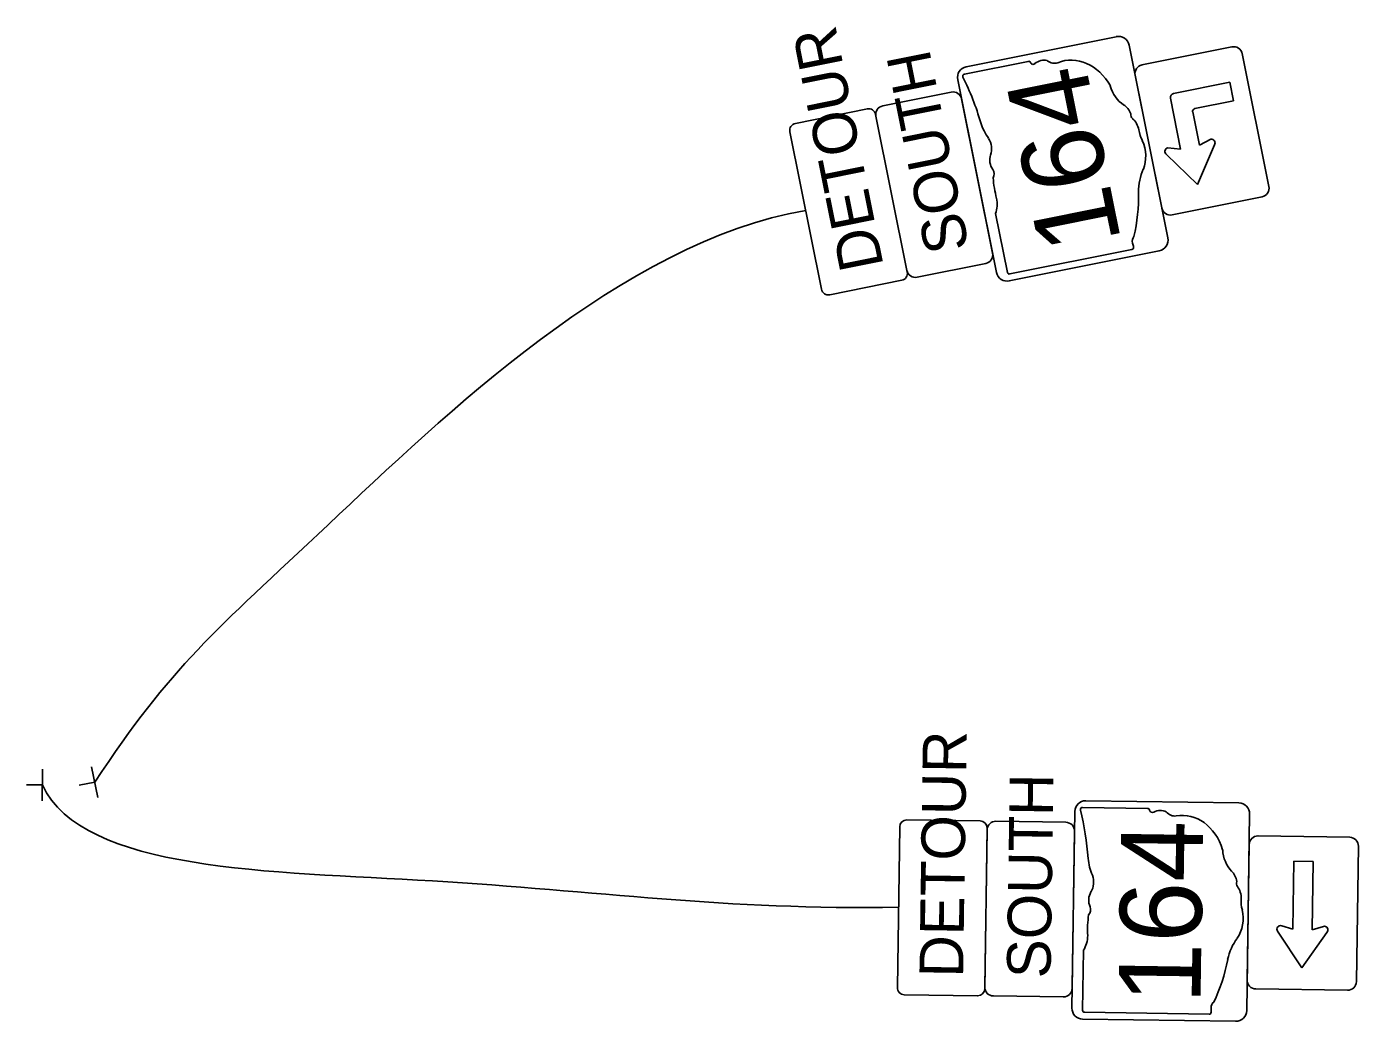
# Model space of a CAD drawing. Extents: x 0 to 1214, y 0 to 883.
# Drawn here: x 203.8 to 356.2, y 531.6 to 645.4 of the extents above; entities that cross this region are included whole.
import ezdxf

# ---------------------------------------------------------------- set-up
doc = ezdxf.new("R2010")
doc.units = 0
for name, color, linetype in [('GM_X_Minor_Lake', 7, 'Continuous'), ('GM_X_Minor_River', 7, 'Continuous'), ('SH_Data', 7, 'Continuous')]:
    doc.layers.add(name, color=color, linetype=linetype)

msp = doc.modelspace()

# ---------------------------------------------------------------- linework, layer by layer
at = {"layer": 'GM_X_Minor_Lake'}
for p, q in [((343.72, 551.84), (343.49, 536.34)), ((355.23, 552.67), (344.73, 552.82)), ((355.99, 536.15), (356.22, 551.65)), ((348.73, 542.14), (348.85, 549.95)), ((348.85, 549.95), (351.03, 549.91)), ((351.03, 549.91), (350.92, 542.1)), ((347.45, 542.55), (348.73, 542.14)), ((350.92, 542.1), (352.21, 542.48)), ((349.76, 537.74), (346.98, 541.92)), ((352.62, 541.78), (349.76, 537.74)), ((344.47, 535.32), (354.97, 535.17))]:
    msp.add_line(p, q, dxfattribs=at)
for centre, radius, start, end in [((344.72, 551.82), 1, 89.1557, 179.1557), ((355.22, 551.67), 1, 359.1557, 89.1557), ((347.32, 542.16), 0.417, 71.9511, 213.7445), ((352.32, 542.08), 0.417, 314.1461, 106.3603), ((344.49, 536.32), 1, 179.1557, 269.1557), ((354.99, 536.17), 1, 269.1557, 359.1557)]:
    msp.add_arc(centre, radius, start, end, dxfattribs=at)
at = {"layer": 'GM_X_Minor_River'}
for p, q in [((331.46, 641.06), (341.75, 643.13)), ((318.44, 641.47), (311.14, 640)), ((318.44, 641.47), (318.44, 641.47)), ((342.93, 642.35), (345.98, 627.15)), ((333.73, 624.69), (330.68, 639.88)), ((341.51, 639.1), (335.08, 637.8)), ((341.94, 636.95), (341.51, 639.1)), ((301.8, 636.38), (309.64, 637.95)), ((310.82, 637.17), (314.37, 619.52)), ((334.71, 637.25), (335.88, 631.43)), ((334.71, 637.25), (334.71, 637.25)), ((337.5, 636.06), (341.94, 636.95)), ((338.03, 631.86), (337.26, 635.69)), ((304.56, 617.55), (301.02, 635.2)), ((339.32, 632.55), (338.03, 631.86)), ((334.27, 630.81), (337.82, 627.36)), ((335.88, 631.43), (334.42, 631.56)), ((337.82, 627.36), (339.75, 631.91)), ((345.2, 625.97), (334.91, 623.9)), ((314.71, 624.05), (316.06, 617.32)), ((316.35, 617.14), (330.3, 619.95)), ((313.58, 618.34), (305.74, 616.77)), ((211.28, 560.74), (211.99, 557.21)), ((205.67, 560.46), (205.62, 556.86)), ((205.65, 558.66), (203.85, 558.69)), ((211.64, 558.97), (209.87, 558.62)), ((332.1, 555.97), (324.65, 556.08)), ((332.09, 555.97), (332.1, 555.97)), ((313.47, 535.53), (313.74, 553.53)), ((314.75, 554.51), (322.75, 554.39)), ((323.74, 553.38), (323.47, 535.38)), ((324.76, 539.74), (324.66, 532.88)), ((322.46, 534.4), (314.46, 534.51)), ((324.9, 532.64), (339.13, 532.43))]:
    msp.add_line(p, q, dxfattribs=at)
for points in [[(311.36, 640.85), (328.52, 644.29)], [(329.99, 643.31), (334.42, 621.26)], [(314.81, 617.32), (310.38, 639.37)], [(300.04, 636.02), (291.8, 634.37)], [(304.6, 617.36), (300.98, 635.39)], [(291.17, 633.42), (294.8, 615.39)], [(333.44, 619.78), (316.28, 616.34)], [(295.74, 614.76), (303.98, 616.41)], [(325.04, 556.86), (342.54, 556.6)], [(312.95, 554.54), (304.55, 554.66)], [(323.44, 533.13), (323.77, 555.63)], [(343.77, 555.33), (343.44, 532.84)], [(303.74, 553.87), (303.47, 535.48)], [(313.47, 535.33), (313.74, 553.73)], [(304.26, 534.66), (312.66, 534.54)], [(342.17, 531.61), (324.67, 531.86)]]:
    msp.add_lwpolyline(points, dxfattribs=at)
for centre, radius, start, end in [((328.76, 643.07), 1.25, 11.3615, 101.3615), ((341.95, 642.15), 1, 11.3615, 101.3615), ((311.6, 639.62), 1.25, 101.3615, 191.3615), ((331.66, 640.08), 1, 101.3615, 191.3615), ((309.84, 636.97), 1, 11.3615, 101.3615), ((335.17, 637.34), 0.469, 101.3615, 191.3615), ((300.19, 635.24), 0.8, 11.3615, 101.3615), ((302, 635.4), 1, 101.3615, 191.3615), ((337.56, 635.75), 0.312, 101.3615, 191.3615), ((291.96, 633.58), 0.8, 101.3615, 191.3615), ((339.4, 632.14), 0.417, 326.3616, 101.3631), ((334.5, 631.15), 0.417, 101.3631, 236.3613), ((345, 626.95), 1, 281.3615, 11.3615), ((334.71, 624.88), 1, 191.3615, 281.3615), ((333.19, 621.01), 1.25, 281.3615, 11.3615), ((313.39, 619.32), 1, 281.3615, 11.3615), ((303.82, 617.2), 0.8, 281.3615, 11.3615), ((305.54, 617.75), 1, 191.3615, 281.3615), ((316.04, 617.56), 1.25, 191.3615, 281.3615), ((295.58, 615.54), 0.8, 191.3615, 281.3615), ((325.02, 555.61), 1.25, 89.1557, 179.1557), ((342.52, 555.35), 1.25, 359.1557, 89.1557), ((304.54, 553.86), 0.8, 89.1557, 179.1557), ((312.94, 553.74), 0.8, 359.1557, 89.1557), ((314.74, 553.51), 1, 89.1557, 179.1557), ((322.74, 553.39), 1, 359.1557, 89.1557), ((304.27, 535.46), 0.8, 179.1557, 269.1557), ((312.67, 535.34), 0.8, 269.1557, 359.1557), ((314.47, 535.51), 1, 179.1557, 269.1557), ((322.47, 535.4), 1, 269.1557, 359.1557), ((324.69, 533.11), 1.25, 179.1557, 269.1557), ((342.19, 532.86), 1.25, 269.1557, 359.1557)]:
    msp.add_arc(centre, radius, start, end, dxfattribs=at)
for centre, major_axis, start_param, end_param in [((318.53, 641.2), (-0.055, 0.274), 5.05454, 6.418171), ((320.42, 639.19), (-0.48, 2.38), 5.934695, 6.695948), ((321.31, 643), (-0.35, 1.73), 2.387724, 3.262537), ((323.8, 635.45), (-1.22, 6.09), 5.101752, 6.440018), ((311.16, 639.74), (-0.051, 0.256), 6.141152, 7.989035), ((318.99, 641.52), (-0.08, 0.396), 1.883978, 3.671073), ((294.11, 628.07), (-4.9, 24.37), 4.814394, 5.042369), ((330.45, 639.46), (-0.67, 3.34), 1.647645, 2.488434), ((328.74, 634.72), (-0.4, 1.97), 4.937069, 5.64225), ((330.61, 635.33), (-0.105, 0.524), 1.147584, 2.315152), ((316.77, 635.85), (-0.99, 4.9), 1.699011, 2.107814), ((329.6, 633.37), (-0.37, 1.86), 4.691044, 5.507374), ((312.71, 631.61), (-0.37, 1.86), 4.081561, 5.145723), ((333.43, 633.88), (-0.58, 2.87), 1.495662, 1.94098), ((329.01, 630.89), (-0.7, 3.49), 4.026481, 4.996735), ((315.32, 630.06), (-0.31, 1.55), 0.950623, 2.079405), ((313.93, 628.64), (-0.15, 0.745), 3.836095, 5.185415), ((322.05, 628.08), (-1.86, 9.27), 1.404758, 1.657858), ((335.6, 626.02), (-1.11, 5.51), 0.823519, 1.323587), ((316.55, 627.65), (-3.54, 17.6), 4.195997, 4.488961), ((312.77, 625.33), (-0.52, 2.58), 4.042523, 4.731795), ((330.28, 620.22), (-0.054, 0.269), 3.00124, 4.508301), ((330.96, 620.84), (-0.148, 0.739), 0.519207, 1.627899), ((328.84, 619.97), (-0.41, 2.05), 4.665946, 4.897461), ((316.26, 617.4), (-0.053, 0.266), 1.712693, 3.28349), ((324.62, 555.82), (0.004, 0.261), 6.141152, 7.989035), ((305.48, 548.02), (0.37, 24.85), 4.814394, 5.042369), ((332.12, 555.7), (0.004, 0.279), 5.05454, 6.418171), ((332.64, 555.91), (0.006, 0.404), 1.883978, 3.671073), ((333.54, 553.32), (0.04, 2.42), 5.934695, 6.695948), ((335.22, 556.86), (0.03, 1.76), 2.387724, 3.262537), ((336.05, 548.96), (0.09, 6.22), 5.101752, 6.440018), ((329.27, 550.84), (0.07, 5), 1.699011, 2.107814), ((343.41, 551.47), (0.05, 3.4), 1.647645, 2.488434), ((340.73, 547.2), (0.03, 2.01), 4.937069, 5.64225), ((324.41, 547.55), (0.03, 1.9), 4.081561, 5.145723), ((342.69, 547.4), (0.008, 0.535), 1.147584, 2.315152), ((341.29, 545.7), (0.03, 1.9), 4.691044, 5.507374), ((326.63, 545.48), (0.02, 1.58), 0.950623, 2.079405), ((345.14, 545.38), (0.04, 2.93), 1.495662, 1.94098), ((324.97, 544.39), (0.011, 0.76), 3.836095, 5.185415), ((340.19, 543.4), (0.05, 3.56), 4.026481, 4.996735), ((332.79, 542.13), (0.14, 9.45), 1.404758, 1.657858), ((323.14, 541.4), (0.04, 2.63), 4.042523, 4.731795), ((345.6, 537.24), (0.08, 5.62), 0.823519, 1.323587), ((327.32, 542.86), (0.26, 17.95), 4.195997, 4.488961), ((339.97, 533.16), (0.011, 0.754), 0.519207, 1.627899), ((324.88, 532.91), (0.004, 0.271), 1.712693, 3.28349), ((339.17, 532.7), (0.004, 0.274), 3.00124, 4.508301), ((337.71, 532.76), (0.03, 2.09), 4.665946, 4.897461)]:
    msp.add_ellipse(centre, major_axis=major_axis, ratio=0.8, start_param=start_param, end_param=end_param, dxfattribs=at)
at = {"layer": 'SH_Data'}
for points in [[(292.99, 624.4), (272.05, 620.86), (230.48, 580.31), (220.37, 572.25), (211.64, 558.97)], [(303.61, 544.68), (284.02, 544.3), (253.46, 548.86), (210.27, 548.7), (205.65, 558.66)]]:
    msp.add_open_spline(points, degree=3, dxfattribs=at)

# ---------------------------------------------------------------- texts
at = {"layer": 'GM_X_Minor_River'}
for s, height, rotation, p in [('DETOUR', 5, 101.3615, (301.91, 618.07)), ('SOUTH', 5, 101.3615, (311.7, 620.09)), ('164', 9.375, 101.3615, (329.09, 620.88)), ('DETOUR', 5, 89.1557, (310.99, 536.6)), ('SOUTH', 5, 89.1557, (320.99, 536.51)), ('164', 9.375, 89.1557, (338.15, 533.59))]:
    msp.add_text(s, height=height, rotation=rotation, dxfattribs=at).set_placement(p)

doc.saveas('drawing.dxf')
